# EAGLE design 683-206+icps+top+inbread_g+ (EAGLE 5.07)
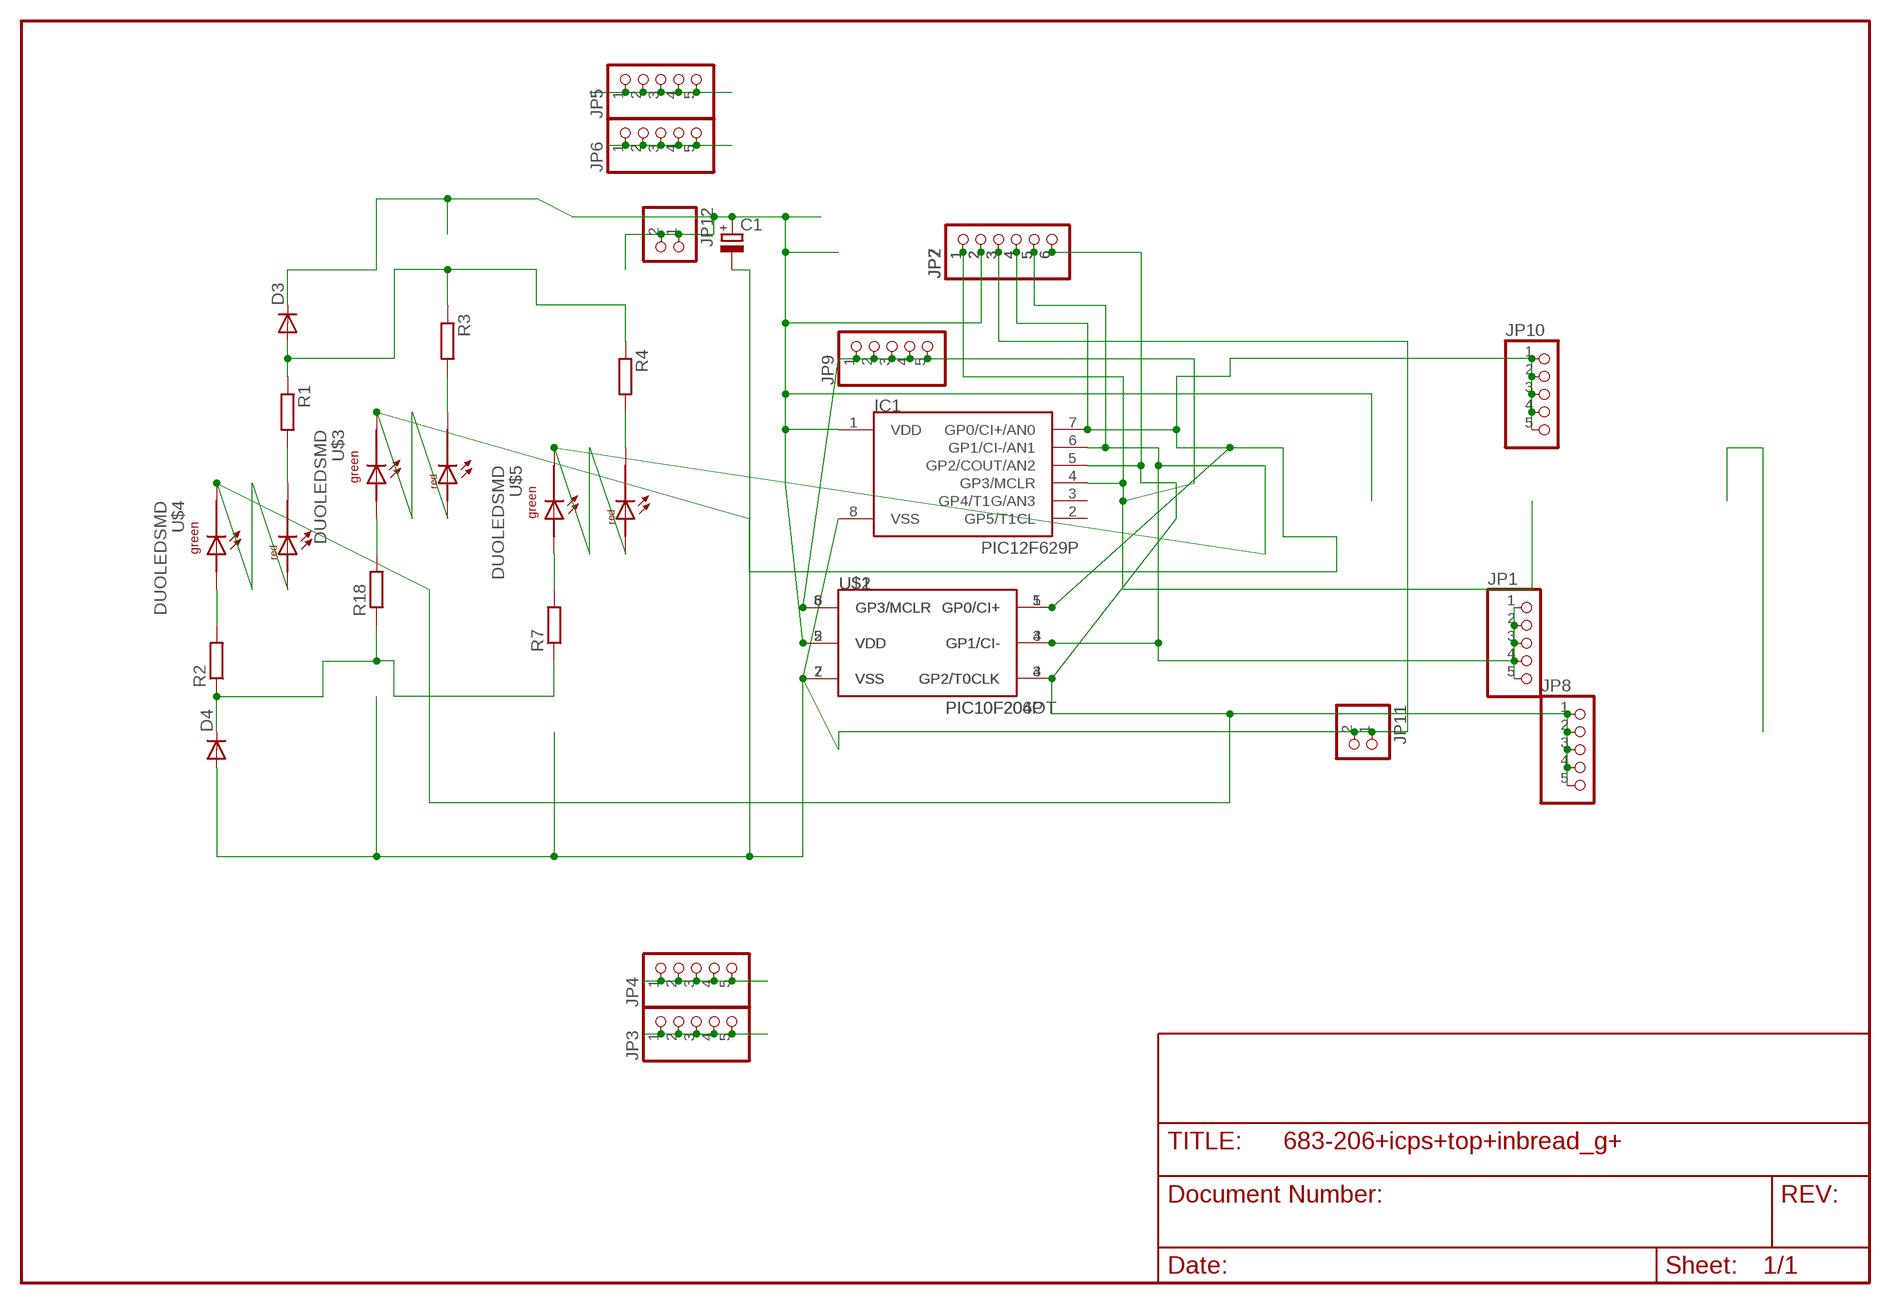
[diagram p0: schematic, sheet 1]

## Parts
C1  CPOL-EUE5-5  [E5-5]
D3  DIODE-MINIMELF  [MINIMELF]
D4  DIODE-MINIMELF  [MINIMELF]
IC1  PIC12F629P  [DIL8]
JP1  PINHD-1X5  [1X05]
JP2  PINHD-1X6  [1X06]
JP3  PINHD-1X5  [1X05]
JP4  PINHD-1X5  [1X05]
JP5  PINHD-1X5  [1X05]
JP6  PINHD-1X5  [1X05]
JP7  PINHD-1X6  [1X06]
JP8  PINHD-1X5  [1X05]
JP9  PINHD-1X5  [1X05]
JP10  PINHD-1X5  [1X05]
JP11  PINHD-1X2  [1X02]
JP12  PINHD-1X2  [1X02]
R1  R-EU_R1206  [R1206]
R2  R-EU_R1206  [R1206]
R3  R-EU_R1206  [R1206]
R4  R-EU_R1206  [R1206]
R7  R-EU_R1206  [R1206]
R18  R-EU_R1206  [R1206]
U$1  PIC10F206P  [DIL8]
U$2  PIC10F204OT  [SOT23-6]
U$3  DUOLEDSMD  [DUOLEDSMD]
U$4  DUOLEDSMD  [DUOLEDSMD]
U$5  DUOLEDSMD  [DUOLEDSMD]

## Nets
GP0: IC1.7(GP0/CI+/AN0) JP2.4 JP7.4 JP10.1 JP10.2 JP10.3 JP10.4 JP10.5 U$1.5(GP0/CI+) U$2.1(GP0/CI+) U$3.ARED U$3.CGRN
GP1: IC1.6(GP1/CI-/AN1) JP1.1 JP1.2 JP1.3 JP1.4 JP1.5 JP2.5 JP7.5 U$1.4(GP1/CI-) U$2.3(GP1/CI-) U$5.ARED U$5.CGRN
GP2: IC1.5(GP2/COUT/AN2) JP2.6 JP7.6 JP8.1 JP8.2 JP8.3 JP8.4 JP8.5 U$1.3(GP2/T0CLK) U$2.4(GP2/T0CLK) U$4.ARED U$4.CGRN
GP3: IC1.4(GP3/MCLR) JP2.1 JP7.1 JP9.1 JP9.2 JP9.3 JP9.4 JP9.5 U$1.8(GP3/MCLR) U$2.6(GP3/MCLR)
N$1: JP4.1 JP4.2 JP4.3 JP4.4 JP4.5
N$2: JP3.1 JP3.2 JP3.3 JP3.4 JP3.5
N$3: R2.2 U$4.AGRN
N$4: JP6.1 JP6.2 JP6.3 JP6.4 JP6.5
N$5: JP5.1 JP5.2 JP5.3 JP5.4 JP5.5
N$6: R1.2 U$4.CRED
N$7: D4.C R2.1 R7.1 R18.1
N$8: D3.A R1.1 R3.1 R4.1
N$9: R3.2 U$3.CRED
N$10: R18.2 U$3.AGRN
N$11: R7.2 U$5.AGRN
N$12: R4.2 U$5.CRED
VDD: C1.+ D3.C IC1.1(VDD) JP2.2 JP7.2 JP12.1 JP12.2 U$1.2(VDD) U$2.5(VDD)
VSS: C1.- D4.A IC1.8(VSS) JP2.3 JP7.3 JP11.1 JP11.2 U$1.7(VSS) U$2.2(VSS)
Unconnected: IC1.2(GP5/T1CL) IC1.3(GP4/T1G/AN3)

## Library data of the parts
C1 = rcl:CPOL-EU: POLARIZED CAPACITOR, European symbol
D3 D4 = diode:DIODE-: DIODE
IC1 = microchip-5:PIC12F6*: uPC nW 1k Program Flash memory 2x Timer Comparator 10b A/D converter/ 4xIN
JP1 JP3-JP6 JP8-JP10 = pinhead(2):PINHD-1X5: PIN HEADER
JP2 JP7 = pinhead:PINHD-1X6: PIN HEADER
JP11 JP12 = pinhead(2):PINHD-1X2: PIN HEADER
R1-R4 R7 R18 = rcl:R-EU_: RESISTOR, European symbol
U$1 U$2 = microchip-5:PIC10F2*: uPC nW 0,25/0,5k Program Flash memory Comparator
U$3-U$5 = led:DUOLEDSMD

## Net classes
0 default: width 0.3 mm, drill 0.6 mm, clearance 0.2 mm
1 power: width 0.4 mm, drill 0.6 mm, clearance 0.2 mm

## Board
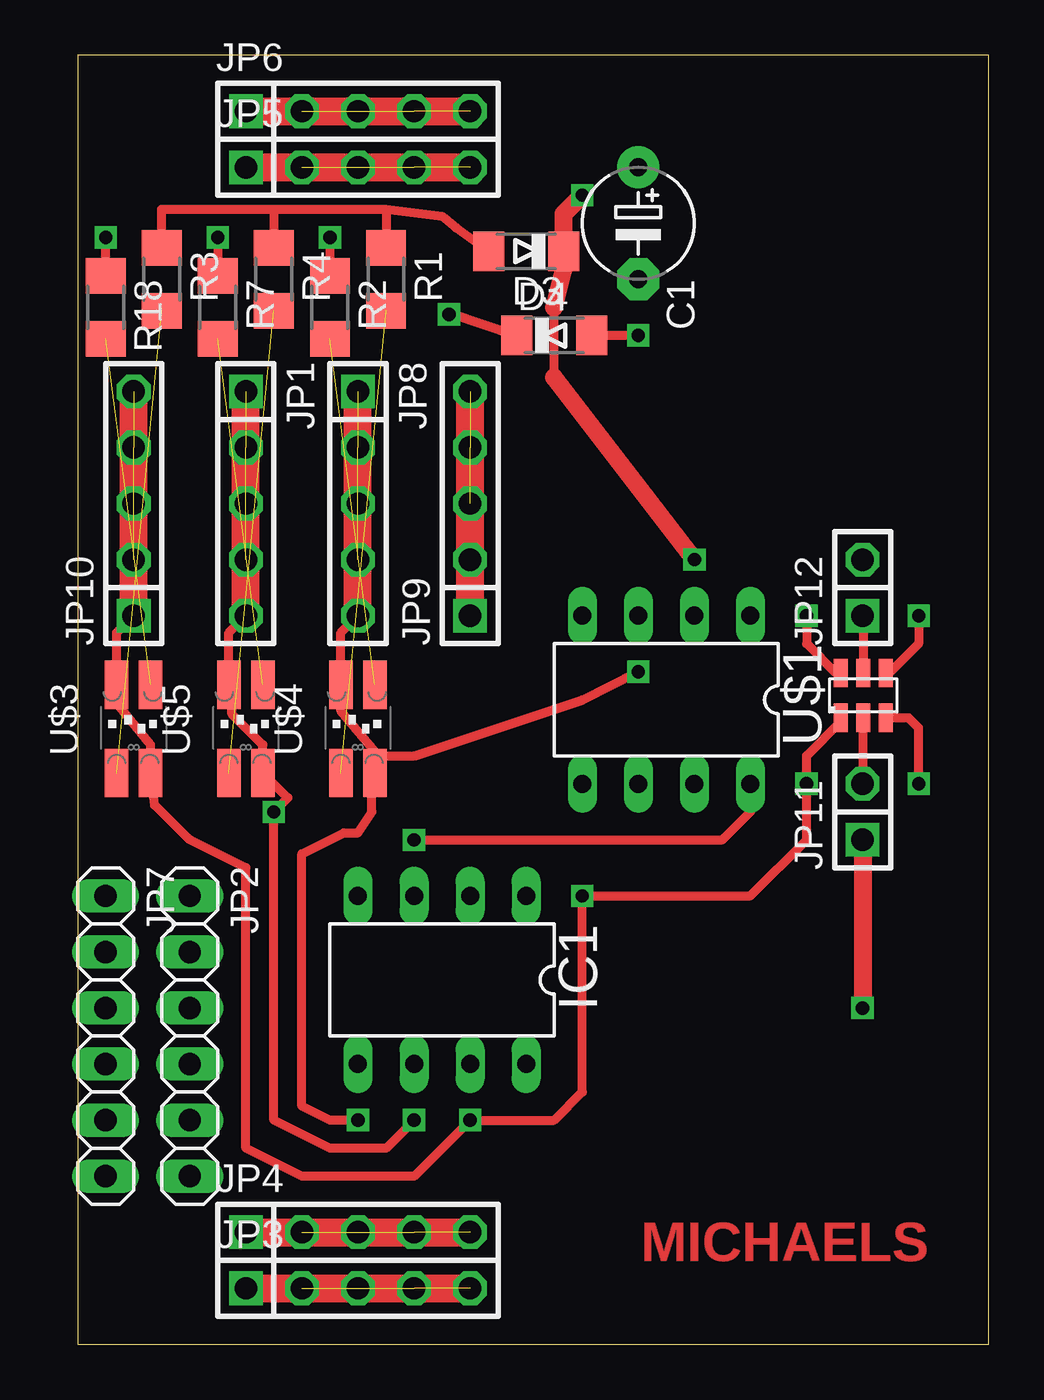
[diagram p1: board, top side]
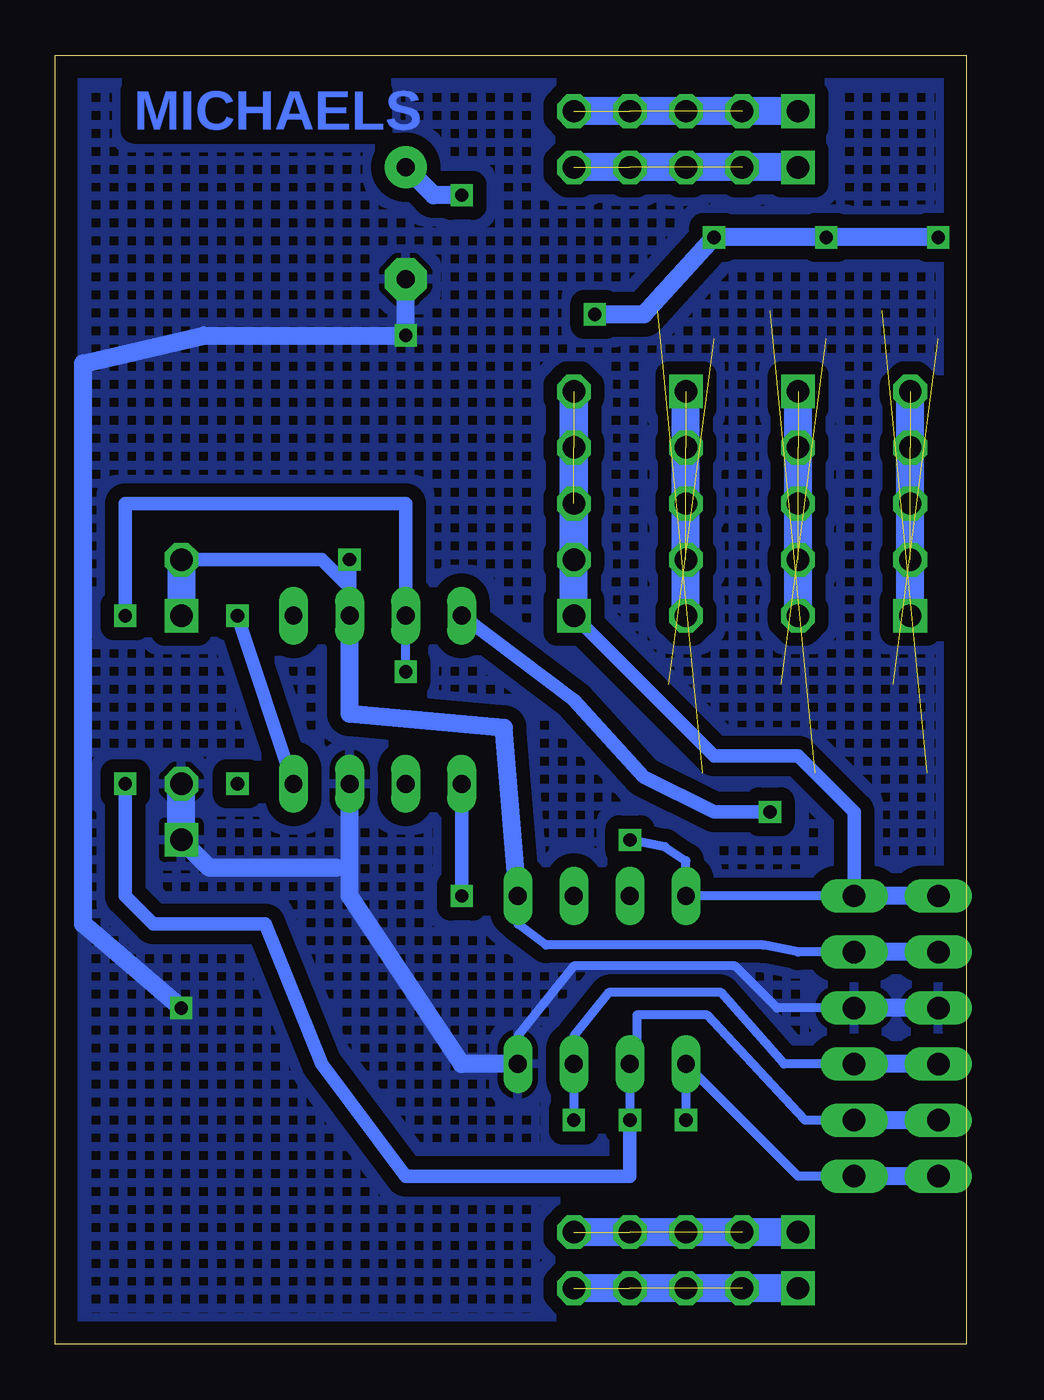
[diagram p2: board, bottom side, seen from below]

Size 41.27 x 58.42 mm. Coordinates in mm from the lower left corner, seen from the top.
Outline: 0,0 41.27,0 41.27,58.42 0,58.42 0,0
Copper layers (1*16): Top 0.035mm / dielectric 1.5mm / Bottom 0.035mm
Design rules "default": minimum track width 10mil, minimum drill 24mil, track to track 8mil, track to pad 8mil, pad to pad 8mil, via to via 8mil, smd to smd 8mil, copper to edge 40mil, drill to drill 8mil, minimum pad ring 10mil, minimum via ring 8mil, stop-mask expansion 4mil, vias tented up to drill 0mil, thermal gap 10mil

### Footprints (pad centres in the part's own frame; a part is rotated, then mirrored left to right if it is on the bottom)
E5-5 = drill 0.813 pad 1.905 round: + -2.54,0 | drill 0.813 pad 1.905 octagon: - 2.54,0
MINIMELF = smd 1.4 x 1.8: A 1.7,0; C -1.7,0
DIL8 = drill 0.813 long: 1 -3.81,-3.81; 2 -1.27,-3.81; 3 1.27,-3.81; 4 3.81,-3.81; 5 3.81,3.81; 6 1.27,3.81; 7 -1.27,3.81; 8 -3.81,3.81
1X05 = drill 1.016 square: 1 -5.08,0 | drill 1.016 octagon: 2 -2.54,0; 3 0,0; 4 2.54,0; 5 5.08,0
1X06 = drill 1.016 long: 1 -6.35,0; 2 -3.81,0; 3 -1.27,0; 4 1.27,0; 5 3.81,0; 6 6.35,0
1X02 = drill 1.016 square: 1 -1.27,0 | drill 1.016 octagon: 2 1.27,0
R1206 = smd 1.6 x 1.803: 1 -1.422,0; 2 1.422,0
SOT23-6 = smd 0.635 x 1.27: 1 -1.016,-1.016; 2 0,-1.016; 3 1.016,-1.016; 4 1.016,1.016; 5 0,1.016; 6 -1.016,1.016
DUOLEDSMD = smd 1.067 x 2.184: AGRN 0.77,1.95; ARED -0.77,1.95; CGRN 0.77,-2.05; CRED -0.77,-2.05

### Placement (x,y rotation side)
C1  25.4,50.8 270 top
D3  20.32,49.53 180 top
D4  21.59,45.72 0 top
IC1  16.51,16.51 180 top
JP1  7.62,38.1 270 top
JP2  5.08,13.97 270 top
JP3  12.7,2.54 0 top
JP4  12.7,5.08 0 top
JP5  12.7,53.34 0 top
JP6  12.7,55.88 0 top
JP7  1.27,13.97 270 top
JP8  12.7,38.1 270 top
JP9  17.78,38.1 90 top
JP10  2.54,38.1 90 top
JP11  35.56,24.13 90 top
JP12  35.56,34.29 90 top
R1  13.97,48.26 270 top
R2  11.43,46.99 270 top
R3  3.81,48.26 270 top
R4  8.89,48.26 270 top
R7  6.35,46.99 270 top
R18  1.27,46.99 270 top
U$1  26.67,29.21 180 top
U$2  35.59,29.41 0 top
U$3  2.54,27.94 0 top
U$4  12.7,27.94 0 top
U$5  7.62,27.94 0 top

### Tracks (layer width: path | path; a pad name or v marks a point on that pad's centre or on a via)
GP0  (via drill 0.6)  (3 unrouted)
  Top 0.406: JP10.1 1.77,32.25 U$3.ARED 1.91,29.07 1.91,28.89 3.31,27.17 U$3.CGRN 3.49,24.44 3.81,24.13 5.08,22.86 7.62,21.59 7.62,8.89 10.16,7.62 15.24,7.62 v17.78,10.16 21.59,10.16 22.86,11.43 v22.86,20.32 30.48,20.32 33.02,22.86 v33.02,25.4 33.02,26.67 34.57,28.22 U$2.1
  Top 1.27: JP10.1 JP10.5
  Bottom 0.406: JP2.4 8.26,12.7 11.11,15.94 16.19,15.94 17.78,13.97 IC1.7 v17.78,10.16
  Bottom 0.61: v22.86,20.32 U$1.5
  Bottom 0.813: JP7.4 JP2.4
  Bottom 1.27: JP10.1 JP10.5
GP1  (via drill 0.6)  (3 unrouted)
  Top 0.406: v15.24,10.16 13.97,8.89 11.43,8.89 8.89,10.16 v8.89,24.12 9.52,24.76 | 9.52,24.76 U$5.CGRN 8.39,27.17 6.99,28.57 6.99,28.75 U$5.ARED 6.85,32.25 JP1.5 | 9.52,24.76 v8.89,24.13 | U$2.3 37.65,28.39 38.1,27.94 v38.1,25.4
  Top 1.27: JP1.5 JP1.1
  Bottom 0.406: JP2.5 7.3,10.16 11.75,14.92 14.92,14.92 14.92,13.02 IC1.6 v15.24,10.16
  Bottom 0.61: U$1.4 17.78,29.21 14.61,25.72 11.43,24.13 v8.89,24.13 | v38.1,25.4 38.1,20.32 36.83,19.05 31.75,19.05 29.21,12.7 25.4,7.62 15.24,7.62 v15.24,10.16
  Bottom 0.813: JP7.5 JP2.5
  Bottom 1.27: JP1.5 JP1.1
GP2  (via drill 0.6)  (3 unrouted)
  Top 0.406: v12.7,10.16 11.43,10.16 10.16,10.79 10.16,22.23 12.06,23.18 12.7,23.18 13.34,24.13 13.34,25.75 U$4.CGRN 13.47,26.85 | v25.4,30.48 22.86,29.21 15.24,26.67 13.93,26.67 13.47,26.85 | JP8.5 11.93,32.25 U$4.ARED 11.93,28.71 13.47,26.85 | U$2.4 36.78,30.43 38.1,31.75 v38.1,33.02
  Top 1.27: JP8.5 JP8.1
  Bottom 0.406: JP2.6 7.62,7.62 IC1.5 v12.7,10.16 | v25.4,30.48 U$1.3
  Bottom 0.61: v38.1,33.02 38.1,38.1 25.4,38.1 U$1.3
  Bottom 0.813: JP7.6 JP2.6
  Bottom 1.27: JP8.5 JP8.1
GP3  (via drill 0.6)  (2 unrouted)
  Top 0.406: v15.24,22.86 29.21,22.86 30.48,24.13 U$1.8 | U$2.6 34.34,30.43 33.02,31.75 v33.02,33.02
  Top 1.27: JP9.1 JP9.5
  Bottom 0.406: JP2.1 IC1.4 12.7,21.91 13.65,22.54 v15.24,22.86
  Bottom 0.61: JP9.1 11.43,26.67 7.62,26.67 5.08,24.13 JP2.1 | U$1.8 v33.02,33.02
  Bottom 0.813: JP7.1 JP2.1
  Bottom 1.27: JP9.2 JP9.5 JP9.1
N$1  (3 unrouted)
  Top 1.27: JP4.1 JP4.5
  Bottom 1.27: JP4.1 JP4.5
N$2  (3 unrouted)
  Top 1.27: JP3.1 JP3.5
  Bottom 1.27: JP3.1 JP3.5
N$3  (1 unrouted)
N$4  (3 unrouted)
  Top 1.27: JP6.1 JP6.5
  Bottom 1.27: JP6.1 JP6.5
N$5  (3 unrouted)
  Top 1.27: JP5.1 JP5.5
  Bottom 1.27: JP5.1 JP5.5
N$6  (1 unrouted)
N$7  (via drill 0.6)
  Top 0.406: D4.C 16.89,46.73 v16.83,46.67 | v6.35,50.16 R7.1 | R18.1 v1.27,50.16 | v11.43,50.16 R2.1
  Bottom 0.813: v16.83,46.67 14.61,46.67 v11.43,50.16 v6.35,50.16 v1.27,50.16
N$8
  Top 0.406: R3.1 3.81,51.44 8.89,51.44 | 8.89,51.44 R4.1 | 8.89,51.44 13.97,51.44 | 13.97,51.44 R1.1 | 13.97,51.44 16.51,51.12 17.14,50.59 D3.A
N$9  (1 unrouted)
N$10  (1 unrouted)
N$11  (1 unrouted)
N$12  (1 unrouted)
VDD  (via drill 0.6)
  Top 0.406: 21.59,43.81 21.59,46.99 | 22.02,48.69 D3.C | U$2.5 35.59,32.99 JP12.1
  Top 0.813: 21.59,46.99 22.02,48.69 | v27.94,35.56 21.59,43.81 | D3.C 22.02,51.23 v22.86,52.07
  Bottom 0.406: JP2.2 7.62,17.78 9.21,18.1 19.05,18.1 20.32,19.05 IC1.1 | U$1.2 27.94,34.29
  Bottom 0.61: 27.94,34.29 29.21,35.56 JP12.2 | U$1.2 v27.94,35.56
  Bottom 0.813: U$1.2 27.94,28.57 20.95,27.94 IC1.1 | v22.86,52.07 24.13,52.07 C1.+ | JP7.2 JP2.2
  Bottom 1.27: JP12.2 JP12.1
VSS  (via drill 0.6)
  Top 0.406: v25.4,45.72 D4.A | U$2.2 35.59,25.43 JP11.2
  Top 0.813: JP11.1 v35.56,15.24
  Bottom 0.406: JP2.3 8.57,15.24 10.48,17.14 17.78,17.14 20.32,13.97 IC1.8
  Bottom 0.61: 27.94,21.81 28.54,21.59
  Bottom 0.813: IC1.8 22.86,12.7 27.94,20.32 27.94,21.81 U$1.7 | JP11.1 34.29,21.59 28.54,21.59 | v35.56,15.24 40.01,19.05 40.01,44.45 34.55,45.72 v25.4,45.72 C1.- | JP7.3 JP2.3
  Bottom 1.27: JP11.1 JP11.2
  pour Bottom (isolate 0.61, hatched): 0,58.42 40.64,58.42 40.64,0 0,0

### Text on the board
Top: MICHAELS
Bottom: MICHAELS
